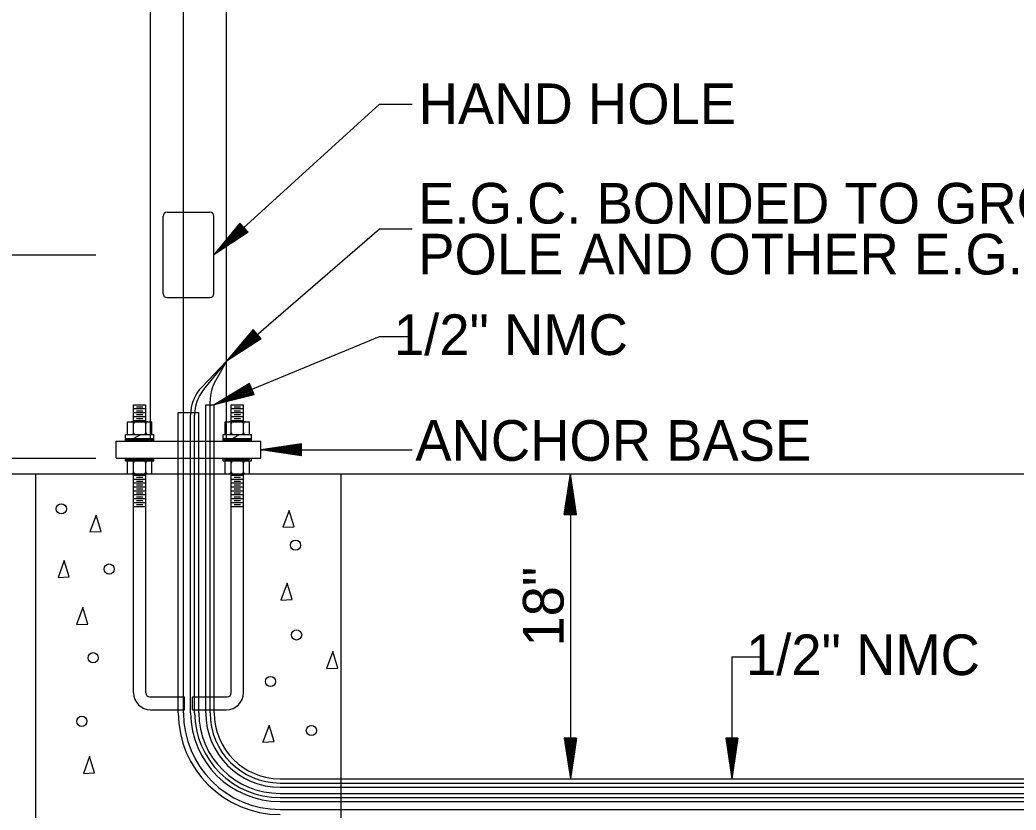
# Model space of a CAD drawing. Extents: x 1370050 to 1370716, y 380076 to 380502.
# Drawn here: x 1370122.9 to 1370196.4, y 380362.8 to 380421.1 of the extents above; entities that cross this region are included whole.
import ezdxf

# ---------------------------------------------------------------- set-up
doc = ezdxf.new("R2010")
doc.units = 0
doc.layers.add('R_Grid', color=7, linetype='Continuous')

msp = doc.modelspace()

# ---------------------------------------------------------------- linework, layer by layer
at = {"layer": 'R_Grid'}
for p, q in [((1370132.544, 380389.975), (1370132.544, 380447.578)), ((1370138.169, 380389.975), (1370138.169, 380447.578)), ((1370134.981, 380369.94), (1370134.981, 380435.908)), ((1370137.231, 380403.725), (1370149.439, 380414.855)), ((1370149.439, 380414.855), (1370151.844, 380414.855)), ((1370133.481, 380400.875), (1370133.481, 380406.575)), ((1370133.781, 380406.875), (1370136.931, 380406.875)), ((1370137.231, 380400.875), (1370137.231, 380406.575)), ((1370139.143, 380406.081), (1370137.231, 380403.725)), ((1370139.193, 380406.025), (1370137.601, 380404.063)), ((1370139.245, 380405.969), (1370137.982, 380404.411)), ((1370138.169, 380395.899), (1370149.439, 380405.649)), ((1370139.296, 380405.914), (1370138.351, 380404.748)), ((1370139.347, 380405.857), (1370138.726, 380405.091)), ((1370139.544, 380405.641), (1370138.726, 380405.091)), ((1370139.399, 380405.801), (1370139.096, 380405.429)), ((1370139.494, 380405.697), (1370139.096, 380405.429)), ((1370139.75, 380405.416), (1370139.143, 380406.081)), ((1370149.439, 380405.649), (1370151.844, 380405.649)), ((1370139.75, 380405.416), (1370137.231, 380403.725)), ((1370139.699, 380405.472), (1370137.601, 380404.063)), ((1370139.648, 380405.528), (1370137.982, 380404.411)), ((1370139.597, 380405.584), (1370138.351, 380404.748)), ((1370119.794, 380403.725), (1370128.531, 380403.725)), ((1370133.781, 380400.575), (1370136.931, 380400.575)), ((1370137.256, 380392.674), (1370149.439, 380397.7)), ((1370140.129, 380398.214), (1370138.169, 380395.899)), ((1370140.722, 380397.537), (1370138.169, 380395.899)), ((1370140.178, 380398.157), (1370138.546, 380396.229)), ((1370140.673, 380397.593), (1370138.546, 380396.229)), ((1370140.229, 380398.1), (1370138.934, 380396.569)), ((1370140.622, 380397.651), (1370138.934, 380396.569)), ((1370140.278, 380398.043), (1370139.31, 380396.898)), ((1370140.573, 380397.707), (1370139.31, 380396.898)), ((1370140.329, 380397.986), (1370139.692, 380397.233)), ((1370140.521, 380397.766), (1370139.692, 380397.233)), ((1370140.379, 380397.928), (1370140.069, 380397.563)), ((1370140.472, 380397.822), (1370140.069, 380397.563)), ((1370140.722, 380397.537), (1370140.129, 380398.214)), ((1370149.439, 380397.7), (1370151.844, 380397.7)), ((1370138.169, 380395.899), (1370136.336, 380393.98)), ((1370138.169, 380395.899), (1370136.471, 380393.793)), ((1370138.169, 380395.899), (1370137.335, 380394.431)), ((1370139.858, 380394.234), (1370137.256, 380392.674)), ((1370139.886, 380394.165), (1370137.719, 380392.865)), ((1370139.916, 380394.094), (1370138.196, 380393.062)), ((1370139.944, 380394.025), (1370138.658, 380393.252)), ((1370139.973, 380393.954), (1370139.128, 380393.446)), ((1370140.003, 380393.883), (1370139.591, 380393.637)), ((1370140.201, 380393.402), (1370139.858, 380394.234)), ((1370140.201, 380393.402), (1370137.256, 380392.674)), ((1370140.173, 380393.472), (1370137.719, 380392.865)), ((1370140.143, 380393.542), (1370138.196, 380393.062)), ((1370140.115, 380393.612), (1370138.658, 380393.252)), ((1370140.085, 380393.684), (1370139.128, 380393.446)), ((1370140.056, 380393.753), (1370139.591, 380393.637)), ((1370131.306, 380392.674), (1370132.206, 380392.674)), ((1370131.306, 380391.424), (1370131.306, 380392.674)), ((1370131.306, 380392.386), (1370132.206, 380392.386)), ((1370131.531, 380392.524), (1370131.981, 380392.524)), ((1370132.206, 380391.424), (1370132.206, 380392.674)), ((1370136.631, 380369.94), (1370136.631, 380392.674)), ((1370136.631, 380392.674), (1370137.256, 380392.674)), ((1370136.944, 380369.94), (1370136.944, 380392.949)), ((1370137.256, 380369.94), (1370137.256, 380392.674)), ((1370138.506, 380392.674), (1370139.406, 380392.674)), ((1370138.506, 380391.424), (1370138.506, 380392.674)), ((1370138.506, 380392.386), (1370139.406, 380392.386)), ((1370138.731, 380392.524), (1370139.181, 380392.524)), ((1370139.406, 380391.424), (1370139.406, 380392.674)), ((1370131.306, 380392.097), (1370132.206, 380392.097)), ((1370131.306, 380391.809), (1370132.206, 380391.809)), ((1370131.531, 380392.236), (1370131.981, 380392.236)), ((1370131.531, 380391.947), (1370131.981, 380391.947)), ((1370131.531, 380391.659), (1370131.981, 380391.659)), ((1370134.606, 380369.94), (1370134.606, 380392.097)), ((1370134.606, 380392.097), (1370136.106, 380392.097)), ((1370135.506, 380369.94), (1370135.506, 380391.908)), ((1370135.806, 380369.94), (1370135.806, 380391.91)), ((1370136.106, 380369.94), (1370136.106, 380392.097)), ((1370138.506, 380392.097), (1370139.406, 380392.097)), ((1370138.506, 380391.809), (1370139.406, 380391.809)), ((1370138.731, 380392.236), (1370139.181, 380392.236)), ((1370138.731, 380391.947), (1370139.181, 380391.947)), ((1370138.731, 380391.659), (1370139.181, 380391.659)), ((1370130.856, 380390.477), (1370130.856, 380391.424)), ((1370130.856, 380391.424), (1370132.656, 380391.424)), ((1370131.306, 380391.52), (1370132.206, 380391.52)), ((1370131.306, 380390.477), (1370131.306, 380391.424)), ((1370132.206, 380390.477), (1370132.206, 380391.424)), ((1370132.656, 380390.477), (1370132.656, 380391.424)), ((1370138.056, 380390.477), (1370138.056, 380391.424)), ((1370138.056, 380391.424), (1370139.856, 380391.424)), ((1370138.506, 380391.52), (1370139.406, 380391.52)), ((1370138.506, 380390.477), (1370138.506, 380391.424)), ((1370139.406, 380390.477), (1370139.406, 380391.424)), ((1370139.856, 380390.477), (1370139.856, 380391.424)), ((1370130.706, 380389.975), (1370130.706, 380390.477)), ((1370130.706, 380390.477), (1370132.806, 380390.477)), ((1370130.706, 380390.175), (1370132.806, 380390.175)), ((1370130.706, 380390.071), (1370130.811, 380390.175)), ((1370130.717, 380389.975), (1370130.917, 380390.175)), ((1370130.823, 380389.975), (1370131.023, 380390.175)), ((1370130.929, 380389.975), (1370131.129, 380390.175)), ((1370131.035, 380389.975), (1370131.235, 380390.175)), ((1370131.304, 380390.173), (1370131.831, 380390.468)), ((1370131.306, 380390.021), (1370131.46, 380390.175)), ((1370131.306, 380390.127), (1370131.354, 380390.175)), ((1370131.366, 380389.975), (1370131.566, 380390.175)), ((1370131.473, 380389.975), (1370131.673, 380390.175)), ((1370131.579, 380389.975), (1370131.779, 380390.175)), ((1370131.685, 380389.975), (1370131.885, 380390.175)), ((1370131.791, 380389.975), (1370131.991, 380390.175)), ((1370131.897, 380389.975), (1370132.097, 380390.175)), ((1370132.003, 380389.975), (1370132.203, 380390.175)), ((1370132.206, 380390.05), (1370132.332, 380390.175)), ((1370132.206, 380390.156), (1370132.226, 380390.175)), ((1370132.238, 380389.975), (1370132.438, 380390.175)), ((1370132.344, 380389.975), (1370132.544, 380390.175)), ((1370132.544, 380389.985), (1370132.734, 380390.175)), ((1370132.544, 380390.091), (1370132.628, 380390.175)), ((1370132.806, 380389.975), (1370132.806, 380390.477)), ((1370137.906, 380389.975), (1370137.906, 380390.477)), ((1370137.906, 380390.477), (1370140.006, 380390.477)), ((1370137.906, 380390.175), (1370140.006, 380390.175)), ((1370137.928, 380389.975), (1370138.128, 380390.175)), ((1370137.942, 380390.095), (1370138.022, 380390.175)), ((1370138.169, 380390.037), (1370138.308, 380390.175)), ((1370138.169, 380390.143), (1370138.201, 380390.175)), ((1370138.214, 380389.975), (1370138.414, 380390.175)), ((1370138.506, 380390.028), (1370138.654, 380390.175)), ((1370138.506, 380390.134), (1370138.548, 380390.175)), ((1370138.56, 380389.975), (1370138.76, 380390.175)), ((1370138.598, 380390.176), (1370139.09, 380390.471)), ((1370138.666, 380389.975), (1370138.866, 380390.175)), ((1370138.772, 380389.975), (1370138.972, 380390.175)), ((1370138.878, 380389.975), (1370139.078, 380390.175)), ((1370138.984, 380389.975), (1370139.184, 380390.175)), ((1370139.09, 380389.975), (1370139.29, 380390.175)), ((1370139.196, 380389.975), (1370139.396, 380390.175)), ((1370139.406, 380390.062), (1370139.52, 380390.175)), ((1370139.406, 380390.168), (1370139.413, 380390.175)), ((1370139.426, 380389.975), (1370139.626, 380390.175)), ((1370139.532, 380389.975), (1370139.732, 380390.175)), ((1370139.638, 380389.975), (1370139.838, 380390.175)), ((1370139.744, 380389.975), (1370139.944, 380390.175)), ((1370140.006, 380389.975), (1370140.006, 380390.477)), ((1370130.031, 380388.725), (1370130.031, 380389.975)), ((1370130.031, 380389.975), (1370140.681, 380389.975)), ((1370131.141, 380389.975), (1370131.306, 380390.14)), ((1370131.247, 380389.975), (1370131.306, 380390.034)), ((1370132.109, 380389.975), (1370132.206, 380390.073)), ((1370132.45, 380389.975), (1370132.544, 380390.069)), ((1370132.64, 380389.975), (1370132.806, 380390.142)), ((1370132.746, 380389.975), (1370132.806, 380390.036)), ((1370138.034, 380389.975), (1370138.169, 380390.11)), ((1370138.14, 380389.975), (1370138.169, 380390.004)), ((1370138.32, 380389.975), (1370138.506, 380390.162)), ((1370138.426, 380389.975), (1370138.506, 380390.056)), ((1370139.302, 380389.975), (1370139.406, 380390.079)), ((1370139.85, 380389.975), (1370139.97, 380390.096)), ((1370139.956, 380389.975), (1370139.995, 380390.014)), ((1370140.681, 380388.725), (1370140.681, 380389.975)), ((1370143.681, 380389.8), (1370140.681, 380389.35)), ((1370143.681, 380389.725), (1370141.182, 380389.35)), ((1370143.681, 380389.649), (1370141.698, 380389.35)), ((1370143.681, 380389.574), (1370142.198, 380389.35)), ((1370143.681, 380389.497), (1370142.706, 380389.35)), ((1370143.681, 380388.9), (1370143.681, 380389.8)), ((1370119.794, 380388.725), (1370128.531, 380388.725)), ((1370130.031, 380388.725), (1370140.681, 380388.725)), ((1370130.706, 380388.525), (1370130.706, 380388.725)), ((1370130.706, 380388.625), (1370130.807, 380388.725)), ((1370130.713, 380388.525), (1370130.913, 380388.725)), ((1370130.819, 380388.525), (1370131.019, 380388.725)), ((1370130.925, 380388.525), (1370131.125, 380388.725)), ((1370131.031, 380388.525), (1370131.231, 380388.725)), ((1370131.306, 380388.571), (1370131.461, 380388.725)), ((1370131.306, 380388.677), (1370131.355, 380388.725)), ((1370131.367, 380388.525), (1370131.567, 380388.725)), ((1370131.473, 380388.525), (1370131.673, 380388.725)), ((1370131.579, 380388.525), (1370131.779, 380388.725)), ((1370131.685, 380388.525), (1370131.885, 380388.725)), ((1370131.791, 380388.525), (1370131.991, 380388.725)), ((1370131.897, 380388.525), (1370132.097, 380388.725)), ((1370132.003, 380388.525), (1370132.203, 380388.725)), ((1370132.206, 380388.526), (1370132.406, 380388.725)), ((1370132.206, 380388.632), (1370132.3, 380388.725)), ((1370132.312, 380388.525), (1370132.512, 380388.725)), ((1370132.418, 380388.525), (1370132.618, 380388.725)), ((1370132.524, 380388.525), (1370132.724, 380388.725)), ((1370132.63, 380388.525), (1370132.806, 380388.702)), ((1370132.806, 380388.525), (1370132.806, 380388.725)), ((1370137.906, 380388.525), (1370137.906, 380388.725)), ((1370137.91, 380388.72), (1370137.916, 380388.725)), ((1370137.956, 380388.659), (1370138.022, 380388.725)), ((1370138.001, 380388.599), (1370138.128, 380388.725)), ((1370138.047, 380388.538), (1370138.234, 380388.725)), ((1370138.14, 380388.525), (1370138.34, 380388.725)), ((1370138.246, 380388.525), (1370138.446, 380388.725)), ((1370138.506, 380388.566), (1370138.666, 380388.725)), ((1370138.506, 380388.672), (1370138.56, 380388.725)), ((1370138.572, 380388.525), (1370138.772, 380388.725)), ((1370138.678, 380388.525), (1370138.878, 380388.725)), ((1370138.784, 380388.525), (1370138.984, 380388.725)), ((1370138.89, 380388.525), (1370139.09, 380388.725)), ((1370138.996, 380388.525), (1370139.196, 380388.725)), ((1370139.102, 380388.525), (1370139.302, 380388.725)), ((1370139.208, 380388.525), (1370139.406, 380388.723)), ((1370139.406, 380388.617), (1370139.514, 380388.725)), ((1370139.406, 380388.723), (1370139.408, 380388.725)), ((1370139.42, 380388.525), (1370139.62, 380388.725)), ((1370139.526, 380388.525), (1370139.726, 380388.725)), ((1370139.632, 380388.525), (1370139.832, 380388.725)), ((1370139.739, 380388.525), (1370139.939, 380388.725)), ((1370140.006, 380388.525), (1370140.006, 380388.725)), ((1370140.681, 380389.35), (1370151.844, 380389.35)), ((1370143.681, 380388.9), (1370140.681, 380389.35)), ((1370143.681, 380388.975), (1370141.182, 380389.35)), ((1370143.681, 380389.052), (1370141.698, 380389.35)), ((1370143.681, 380389.127), (1370142.198, 380389.35)), ((1370143.681, 380389.205), (1370142.706, 380389.35)), ((1370143.681, 380389.421), (1370143.207, 380389.35)), ((1370143.681, 380389.28), (1370143.207, 380389.35)), ((1370130.706, 380388.525), (1370132.806, 380388.525)), ((1370130.856, 380387.578), (1370130.856, 380388.525)), ((1370131.137, 380388.525), (1370131.306, 380388.695)), ((1370131.243, 380388.525), (1370131.306, 380388.589)), ((1370131.306, 380387.578), (1370131.306, 380388.525)), ((1370132.11, 380388.525), (1370132.206, 380388.622)), ((1370132.206, 380387.578), (1370132.206, 380388.525)), ((1370132.656, 380387.578), (1370132.656, 380388.525)), ((1370132.736, 380388.525), (1370132.806, 380388.595)), ((1370137.906, 380388.525), (1370140.006, 380388.525)), ((1370138.056, 380387.578), (1370138.056, 380388.525)), ((1370138.352, 380388.525), (1370138.506, 380388.679)), ((1370138.458, 380388.525), (1370138.506, 380388.573)), ((1370138.506, 380387.578), (1370138.506, 380388.525)), ((1370139.314, 380388.525), (1370139.406, 380388.617)), ((1370139.406, 380387.578), (1370139.406, 380388.525)), ((1370139.845, 380388.525), (1370139.891, 380388.572)), ((1370139.856, 380387.578), (1370139.856, 380388.525)), ((1370084.252, 380387.578), (1370242.787, 380387.578)), ((1370124.106, 380342.578), (1370124.106, 380387.578)), ((1370124.106, 380387.578), (1370146.606, 380387.578)), ((1370130.856, 380387.578), (1370132.656, 380387.578)), ((1370131.306, 380371.424), (1370131.306, 380387.578)), ((1370131.306, 380387.482), (1370132.206, 380387.482)), ((1370131.531, 380387.332), (1370131.981, 380387.332)), ((1370132.206, 380371.412), (1370132.206, 380387.578)), ((1370138.056, 380387.578), (1370139.856, 380387.578)), ((1370138.506, 380371.412), (1370138.506, 380387.578)), ((1370138.506, 380387.482), (1370139.406, 380387.482)), ((1370138.731, 380387.332), (1370139.181, 380387.332)), ((1370139.406, 380371.424), (1370139.406, 380387.578)), ((1370146.606, 380342.578), (1370146.606, 380387.578)), ((1370163.07, 380384.578), (1370163.52, 380387.578)), ((1370163.52, 380387.578), (1370163.52, 380365.078)), ((1370163.97, 380384.578), (1370163.52, 380387.578)), ((1370131.306, 380387.193), (1370132.206, 380387.193)), ((1370131.306, 380386.905), (1370132.206, 380386.905)), ((1370131.306, 380386.616), (1370132.206, 380386.616)), ((1370131.531, 380387.043), (1370131.981, 380387.043)), ((1370131.531, 380386.755), (1370131.981, 380386.755)), ((1370138.506, 380387.193), (1370139.406, 380387.193)), ((1370138.506, 380386.905), (1370139.406, 380386.905)), ((1370138.506, 380386.616), (1370139.406, 380386.616)), ((1370138.731, 380387.043), (1370139.181, 380387.043)), ((1370138.731, 380386.755), (1370139.181, 380386.755)), ((1370163.145, 380384.578), (1370163.52, 380387.077)), ((1370163.221, 380384.578), (1370163.52, 380386.561)), ((1370163.895, 380384.578), (1370163.52, 380387.077)), ((1370163.818, 380384.578), (1370163.52, 380386.561)), ((1370131.306, 380386.328), (1370132.206, 380386.328)), ((1370131.306, 380386.039), (1370132.206, 380386.039)), ((1370131.531, 380386.466), (1370131.981, 380386.466)), ((1370131.531, 380386.178), (1370131.981, 380386.178)), ((1370131.531, 380385.889), (1370131.981, 380385.889)), ((1370138.506, 380386.328), (1370139.406, 380386.328)), ((1370138.506, 380386.039), (1370139.406, 380386.039)), ((1370138.731, 380386.466), (1370139.181, 380386.466)), ((1370138.731, 380386.178), (1370139.181, 380386.178)), ((1370138.731, 380385.889), (1370139.181, 380385.889)), ((1370163.296, 380384.578), (1370163.52, 380386.061)), ((1370163.743, 380384.578), (1370163.52, 380386.061)), ((1370131.306, 380385.751), (1370132.206, 380385.751)), ((1370131.306, 380385.463), (1370132.206, 380385.463)), ((1370131.306, 380385.174), (1370132.206, 380385.174)), ((1370131.531, 380385.601), (1370131.981, 380385.601)), ((1370131.531, 380385.313), (1370131.981, 380385.313)), ((1370138.506, 380385.751), (1370139.406, 380385.751)), ((1370138.506, 380385.463), (1370139.406, 380385.463)), ((1370138.506, 380385.174), (1370139.406, 380385.174)), ((1370138.731, 380385.601), (1370139.181, 380385.601)), ((1370138.731, 380385.313), (1370139.181, 380385.313)), ((1370163.374, 380384.578), (1370163.52, 380385.553)), ((1370163.449, 380384.578), (1370163.52, 380385.052)), ((1370163.667, 380384.578), (1370163.52, 380385.553)), ((1370163.59, 380384.578), (1370163.52, 380385.052)), ((1370163.07, 380384.578), (1370163.97, 380384.578)), ((1370175.424, 380374.084), (1370175.424, 380365.078)), ((1370175.424, 380374.084), (1370177.805, 380374.084)), ((1370132.506, 380371.112), (1370135.056, 380371.112)), ((1370135.056, 380370.174), (1370135.056, 380371.112)), ((1370135.656, 380370.174), (1370135.656, 380371.112)), ((1370135.656, 380371.112), (1370138.206, 380371.112)), ((1370132.556, 380370.174), (1370135.056, 380370.174)), ((1370135.656, 380370.174), (1370138.156, 380370.174)), ((1370163.07, 380368.078), (1370163.52, 380365.078)), ((1370163.97, 380368.078), (1370163.07, 380368.078)), ((1370163.145, 380368.078), (1370163.52, 380365.579)), ((1370163.221, 380368.078), (1370163.52, 380366.095)), ((1370163.296, 380368.078), (1370163.52, 380366.594)), ((1370163.373, 380368.078), (1370163.52, 380367.103)), ((1370163.449, 380368.078), (1370163.52, 380367.604)), ((1370163.97, 380368.078), (1370163.52, 380365.078)), ((1370163.665, 380368.078), (1370163.52, 380367.103)), ((1370163.818, 380368.078), (1370163.52, 380366.095)), ((1370163.895, 380368.078), (1370163.52, 380365.579)), ((1370163.743, 380368.078), (1370163.52, 380366.594)), ((1370163.59, 380368.078), (1370163.52, 380367.604)), ((1370174.974, 380368.078), (1370175.424, 380365.078)), ((1370175.874, 380368.078), (1370174.974, 380368.078)), ((1370175.049, 380368.078), (1370175.424, 380365.579)), ((1370175.126, 380368.078), (1370175.424, 380366.095)), ((1370175.201, 380368.078), (1370175.424, 380366.594)), ((1370175.277, 380368.078), (1370175.424, 380367.103)), ((1370175.354, 380368.078), (1370175.424, 380367.604)), ((1370175.874, 380368.078), (1370175.424, 380365.078)), ((1370175.57, 380368.078), (1370175.424, 380367.103)), ((1370175.723, 380368.078), (1370175.424, 380366.095)), ((1370175.799, 380368.078), (1370175.424, 380365.579)), ((1370175.648, 380368.078), (1370175.424, 380366.594)), ((1370175.495, 380368.078), (1370175.424, 380367.604)), ((1370142.106, 380365.078), (1370216.311, 380365.078)), ((1370142.106, 380364.765), (1370215.572, 380364.765)), ((1370142.106, 380364.453), (1370216.311, 380364.453)), ((1370142.106, 380364.003), (1370216.311, 380364.003)), ((1370142.106, 380363.703), (1370220.472, 380363.703)), ((1370142.106, 380363.403), (1370218.291, 380363.403)), ((1370142.106, 380362.815), (1370216.311, 380362.815))]:
    msp.add_line(p, q, dxfattribs=at)
for points in [[(1370128.541, 380384.536), (1370128.087, 380383.291), (1370128.912, 380383.325), (1370128.541, 380384.536)], [(1370142.769, 380384.874), (1370142.315, 380383.629), (1370143.14, 380383.663), (1370142.769, 380384.874)], [(1370126.195, 380381.182), (1370125.741, 380379.937), (1370126.566, 380379.971), (1370126.195, 380381.182)], [(1370142.62, 380379.506), (1370142.166, 380378.261), (1370142.991, 380378.294), (1370142.62, 380379.506)], [(1370127.559, 380377.706), (1370127.105, 380376.461), (1370127.93, 380376.495), (1370127.559, 380377.706)], [(1370145.995, 380374.457), (1370145.541, 380373.212), (1370146.366, 380373.246), (1370145.995, 380374.457)], [(1370141.302, 380369.028), (1370140.848, 380367.783), (1370141.673, 380367.817), (1370141.302, 380369.028)], [(1370128.062, 380366.723), (1370127.608, 380365.478), (1370128.433, 380365.512), (1370128.062, 380366.723)]]:
    msp.add_lwpolyline(points, dxfattribs=at)
for centre in [(1370125.98, 380384.994), (1370143.243, 380382.311), (1370129.5, 380380.55), (1370143.327, 380375.688), (1370128.327, 380374.011), (1370141.4, 380372.25), (1370127.489, 380369.316), (1370144.416, 380368.645)]:
    msp.add_circle(centre, 0.375, dxfattribs=at)
for centre, radius, start, end in [((1370133.781, 380406.575), 0.3, 90, 180), ((1370136.931, 380406.575), 0.3, 360, 90), ((1370133.781, 380400.875), 0.3, 180, 270), ((1370136.931, 380400.875), 0.3, 270, 0), ((1370138.506, 380391.908), 3, 136.323, 180), ((1370139.944, 380392.949), 3, 150.40686, 180), ((1370138.806, 380391.91), 3, 141.11803, 180), ((1370131.156, 380391.274), 0.15, 0, 90), ((1370131.456, 380391.274), 0.15, 90, 180), ((1370132.056, 380391.274), 0.15, 0, 90), ((1370132.356, 380391.274), 0.15, 90, 180), ((1370138.356, 380391.274), 0.15, 0, 90), ((1370138.656, 380391.274), 0.15, 90, 180), ((1370139.256, 380391.274), 0.15, 0, 90), ((1370139.556, 380391.274), 0.15, 90, 180), ((1370131.156, 380390.627), 0.15, 270, 0), ((1370131.456, 380390.627), 0.15, 180, 270), ((1370132.056, 380390.627), 0.15, 270, 0), ((1370132.356, 380390.627), 0.15, 180, 270), ((1370138.356, 380390.627), 0.15, 270, 0), ((1370138.656, 380390.627), 0.15, 180, 270), ((1370139.256, 380390.627), 0.15, 270, 0), ((1370139.556, 380390.627), 0.15, 180, 270), ((1370131.156, 380388.375), 0.15, 0, 90), ((1370131.456, 380388.375), 0.15, 90, 180), ((1370132.056, 380388.375), 0.15, 0, 90), ((1370132.356, 380388.375), 0.15, 90, 180), ((1370138.356, 380388.375), 0.15, 0, 90), ((1370138.656, 380388.375), 0.15, 90, 180), ((1370139.256, 380388.375), 0.15, 0, 90), ((1370139.556, 380388.375), 0.15, 90, 180), ((1370131.156, 380387.728), 0.15, 270, 0), ((1370131.456, 380387.728), 0.15, 180, 270), ((1370132.056, 380387.728), 0.15, 270, 0), ((1370132.356, 380387.728), 0.15, 180, 270), ((1370138.356, 380387.728), 0.15, 270, 0), ((1370138.656, 380387.728), 0.15, 180, 270), ((1370139.256, 380387.728), 0.15, 270, 0), ((1370139.556, 380387.728), 0.15, 180, 270), ((1370132.556, 380371.424), 1.25, 180, 270), ((1370132.506, 380371.412), 0.3, 180, 270), ((1370138.156, 380371.424), 1.25, 270, 0), ((1370138.206, 380371.412), 0.3, 270, 0), ((1370142.106, 380369.94), 7.5, 180, 270), ((1370142.106, 380369.94), 7.125, 180, 270), ((1370142.075, 380369.972), 6.569, 180.29998, 270.29998), ((1370142.075, 380369.972), 6.269, 180.29998, 270.29998), ((1370142.075, 380369.972), 5.969, 180.29998, 270.29998), ((1370142.112, 380369.934), 5.481, 179.93467, 269.93467), ((1370142.112, 380369.934), 5.169, 179.92626, 269.92626), ((1370142.112, 380369.934), 4.856, 179.92626, 269.92626)]:
    msp.add_arc(centre, radius, start, end, dxfattribs=at)

# ---------------------------------------------------------------- texts
for s, height, p in [('HAND HOLE', 3, (1370152.329, 380413.378)), ('E.G.C. BONDED TO GROUND LUG ON ', 2.99999, (1370152.296, 380406.039)), ('POLE AND OTHER E.G.C. CONDUCTORS', 2.99999, (1370152.296, 380402.284)), (' 1/2" NMC ', 3, (1370149.39, 380396.342)), ('ANCHOR BASE', 2.99999, (1370152.08, 380388.538)), (' 1/2" NMC ', 3, (1370175.351, 380372.725))]:
    msp.add_text(s, height=height, dxfattribs=at).set_placement(p)
msp.add_text('18"', height=3, rotation=90, dxfattribs=at).set_placement((1370163.015, 380374.831))

doc.saveas('drawing.dxf')
